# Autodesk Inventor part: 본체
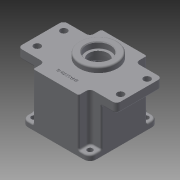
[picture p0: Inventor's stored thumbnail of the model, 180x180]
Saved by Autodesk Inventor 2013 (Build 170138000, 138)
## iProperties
Created: 2015-07
Part Number: 본체
Material: 일반
Document SubType Name: Modeling
Designer: user
Density: 1 g/cm^3
Author: user
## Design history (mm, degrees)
sketch "스케치1"
  geometry: L1 (-45, -45)-(45, -45); L2 (45, -45)-(45, 45); L3 (45, 45)-(-45, 45); L4 (-45, 45)-(-45, -45); L5 (-45, -45)-(45, 45); L6 (45, -45)-(-45, 45); 1 further point
  constraints: 12 end point, 2 midpoint, 2 parallel, 1 horizontal, 1 perpendicular
  dimensions: "d0" = 90 distance of L3.end L2.end; "d1" = 90 distance of L2.end L1.end
extrude "돌출1" new body sketch "스케치1" distance "d2" = 58; taper "d3" = 0 deg
sketch "스케치2"
  geometry: L1 (65, -45)-(-65, -45); L2 (-65, -45)-(-65, 45); L3 (-65, 45)-(65, 45); L4 (65, 45)-(65, -45); L5 (65, -45)-(-65, 45); L6 (-65, -45)-(65, 45); 1 further point
  constraints: 12 end point, 2 midpoint, 2 parallel, 1 horizontal, 1 perpendicular
  dimensions: "d4" = 130 distance of L2.end L3.end; "d5" = 90 distance of L1.end L2.end
extrude "돌출2" join sketch "스케치2" distance "d6" = 12; taper "d7" = 0 deg
sketch "스케치3"
  geometry: L1 (-65, -45)-(65, -45) reference; L2 (65, -45)-(65, 45) reference; L3 (-65, 45)-(-65, -45) reference; L4 (-30, 45)-(-30, 30); L5 (-30, 30)-(-65, 30); L6 (30, 45)-(30, 30); L7 (30, 30)-(65, 30); L8 (-65, 30)-(-65, 45); L9 (-30, 45)-(-65, 45); L10 (30, 45)-(65, 45); L11 (65, 30)-(65, 45); 2 further points
  constraints: 16 end point, 5 perpendicular, 2 collinear, 2 point on line, 1 parallel
  dimensions: "d9" = 60 distance of L4.start L6.start; "d10" = 15 distance of L4.start L4.end; "d12" = 15 distance of L6.start L6.end; "d13" = 35 distance between parallel lines of L2 L6; "d14" = 65 distance from line of point (0, 45) L2; "d15" = 90 distance from line of point (0, 45) L1
extrude "돌출3" cut sketch "스케치3" distance "d16" = 63; taper "d17" = 0 deg
sketch "스케치4"
  geometry: C1 r 40 at (0, 0); 1 further point
  constraints: 1 centre point, 1 coincident
  dimensions: "d18" = 80 diameter of C1
extrude "돌출4" cut sketch "스케치4" distance "d19" = 9; taper "d20" = 0 deg
sketch "스케치5" dims "d21" = 78
  geometry: L1 (0, 0)-(0, 35); L2 (0, 0)-(24.749, 24.749); C1 r 40 at (0, 0) reference; A1 r 4 centre (24.749, 24.749) between (21.809, 27.462) and (27.462, 21.809); A2 r 4 centre (24.749, -24.749) between (27.462, -21.809) and (21.809, -27.462); A3 r 4 centre (-24.749, -24.749) between (-21.809, -27.462) and (-27.462, -21.809); A4 r 4 centre (-24.749, 24.749) between (-27.462, 21.809) and (-21.809, 27.462); A5 r 3.5 centre (-29.836, 19.238) between (-27.412, 21.762) and (-32.777, 21.134); A6 r 3.5 centre (-19.238, 29.836) between (-21.134, 32.777) and (-21.762, 27.412); A7 r 3.5 centre (29.836, 19.238) between (32.777, 21.134) and (27.412, 21.762); A8 r 3.5 centre (19.238, -29.836) between (21.134, -32.777) and (21.762, -27.412); A9 r 3.5 centre (-19.238, -29.836) between (-21.762, -27.412) and (-21.134, -32.777); A10 r 3.5 centre (-29.836, -19.238) between (-32.777, -21.134) and (-27.412, -21.762); A11 r 3.5 centre (29.836, -19.238) between (27.412, -21.762) and (32.777, -21.134); A12 r 3.5 centre (19.238, 29.836) between (21.762, 27.412) and (21.134, 32.777); 1 further point
  constraints: 32 point on circle, 12 centre point, 8 tangent, 4 end point, 3 coincident, 1 point on line, 1 vertical, 22 other
  dimensions: "d23" = 45 deg angle of L2 L1; "d24" = 8 diameter of A1; "d25" = 8 diameter of A2; "d26" = 8 diameter of A3; "d27" = 8 diameter of A4; "d28" = 49.49747 distance of L2.end A2.centre; "d29" = 49.49747 distance of A4.centre L2.end; "d30" = 7 diameter of A5; "d31" = 7 diameter of A6; "d32" = 7 diameter of A7; "d33" = 7 diameter of A8; "d34" = 7 diameter of A9; "d35" = 7 diameter of A10; "d36" = 7 diameter of A11; "d37" = 7 diameter of A12; "d38" = 3.99472 distance from line of A7.end L2; "d39" = 34.77128 distance from line of A11.start L2; "d40" = 3.99472 distance from line of A12.start L2; "d41" = 34.77128 distance from line of A8.end L2; "d42" = 24.74874 distance from line of L1.end L2; "d43" = 34.77128 distance from line of A6.end L2; "d44" = 3.99472 distance from line of A9.start L2; "d45" = 34.77128 distance from line of A5.start L2; "d46" = 3.99472 distance from line of A10.end L2
extrude "돌출5" cut sketch "스케치5" distance "d47" = 52; taper "d48" = 0 deg
sketch "스케치6"
  geometry: L1 (30, 45)-(30, 30) reference; L2 (30, 30)-(65, 30) reference; L3 (65, 30)-(65, -30) reference; L4 (65, -30)-(30, -30) reference; L5 (30, -30)-(30, -45) reference; L6 (30, -45)-(-30, -45) reference; L7 (-30, -45)-(-30, -30) reference; L8 (-30, -30)-(-65, -30) reference; L9 (-65, -30)-(-65, 30) reference; L10 (-65, 30)-(-30, 30) reference; L11 (-30, 30)-(-30, 45) reference; L12 (-30, 45)-(30, 45) reference; L13 (-39, 0)-(39, 0); L14 (-126.492, 11)-(126.492, 11); L15 (-126.492, -20)-(126.492, -20); A1 r 4 centre (-24.749, 24.749) between (-27.462, 21.809) and (-21.809, 27.462) reference; A2 r 3.5 centre (-29.836, 19.238) between (-27.462, 21.809) and (-32.777, 21.134) reference; A3 r 39 centre (0, 0) between (-32.777, 21.134) and (-32.777, -21.134) reference; A4 r 3.5 centre (-29.836, -19.238) between (-32.777, -21.134) and (-27.462, -21.809) reference; A5 r 4 centre (-24.749, -24.749) between (-21.809, -27.462) and (-27.462, -21.809) reference; A6 r 3.5 centre (-19.238, -29.836) between (-21.809, -27.462) and (-21.134, -32.777) reference; A7 r 39 centre (0, 0) between (-21.134, -32.777) and (21.134, -32.777) reference; A8 r 3.5 centre (19.238, -29.836) between (21.134, -32.777) and (21.809, -27.462) reference; A9 r 4 centre (24.749, -24.749) between (27.462, -21.809) and (21.809, -27.462) reference; A10 r 3.5 centre (29.836, -19.238) between (27.462, -21.809) and (32.777, -21.134) reference; A11 r 39 centre (0, 0) between (32.777, -21.134) and (32.777, 21.134) reference; A12 r 3.5 centre (29.836, 19.238) between (32.777, 21.134) and (27.462, 21.809) reference; A13 r 4 centre (24.749, 24.749) between (21.809, 27.462) and (27.462, 21.809) reference; A14 r 3.5 centre (19.238, 29.836) between (21.809, 27.462) and (21.134, 32.777) reference; A15 r 39 centre (0, 0) between (21.134, 32.777) and (-21.134, 32.777) reference; A16 r 3.5 centre (-19.238, 29.836) between (-21.134, 32.777) and (-21.809, 27.462) reference; A17 r 20.5 centre (0, 11) between (7.402, -8.117) and (-7.402, -8.117); A18 r 14 centre (0, -20) between (-7.402, -8.117) and (7.402, -8.117)
  constraints: 6 end point, 6 point on circle, 2 centre point, 2 midpoint, 2 parallel
  dimensions: "d49" = 11 distance between parallel lines of L13 L14; "d51" = 20 distance between parallel lines of L15 L13; "d52" = 41 diameter of A17; "d53" = 28 diameter of A18
extrude "돌출6" join sketch "스케치6" distance "d54" = 7; taper "d55" = 0 deg
fillet "모깎기1" dims "d56" = 3
fillet "모깎기2" dims "d57" = 3
sketch "스케치7"
  geometry: C1 r 17.5 at (0, 11); A1 r 20.5 centre (0, 11) between (11.115, -6.225) and (-11.115, -6.225) reference; 1 further point
  constraints: 1 centre point, 1 coincident
  dimensions: "d58" = 35 diameter of C1
extrude "돌출7" cut sketch "스케치7" distance "d59" = 10; taper "d60" = 0 deg
sketch "스케치8"
  geometry: C1 r 17.5 at (0, 0) reference; C2 r 12.5 at (0, 0); 1 further point
  constraints: 1 centre point, 1 coincident
  dimensions: "d61" = 25 diameter of C2
extrude "돌출8" cut sketch "스케치8" distance "d62" = 5; taper "d63" = 0 deg
sketch "스케치9"
  geometry: C1 r 12.5 at (0, 0) reference; C2 r 16 at (0, 0); 1 further point
  constraints: 1 centre point, 1 coincident
  dimensions: "d64" = 32 diameter of C2
extrude "돌출9" cut sketch "스케치9" distance "d65" = 8; taper "d66" = 0 deg
sketch "스케치10"
  geometry: C1 r 16 at (0, 11) reference; C2 r 25 at (0, 11); 1 further point
  constraints: 1 centre point, 1 coincident
  dimensions: "d67" = 50 diameter of C2
extrude "돌출10" join sketch "스케치10" distance "d68" = 7; taper "d69" = 0 deg
sketch "스케치11"
  geometry: A1 r 4 centre (-24.749, 24.749) between (-27.462, 21.809) and (-21.809, 27.462) reference; A2 r 4 centre (24.749, 24.749) between (21.809, 27.462) and (27.462, 21.809) reference; A3 r 4 centre (24.749, -24.749) between (27.462, -21.809) and (21.809, -27.462) reference; A4 r 4 centre (-24.749, -24.749) between (-21.809, -27.462) and (-27.462, -21.809) reference
hole "구멍1" sketch "스케치11" at (-24.749, 24.749), (-24.749, -24.749), (24.749, -24.749), (24.749, 24.749) diameter "d70" = 3.459; stored, may be unused: countersink angle "d74" = 90 deg, drill point angle "d76" = 118 deg; dims "d71" = 12, "d72" = 4, "d73" = 2, "d75" = 15
fillet "모깎기3" dims "d77" = 8
sketch "스케치12"
  geometry: A1 r 8 centre (-37, 37) between (-37, 45) and (-45, 37) reference; A2 r 8 centre (-37, -37) between (-45, -37) and (-37, -45) reference; A3 r 8 centre (37, -37) between (37, -45) and (45, -37) reference; A4 r 8 centre (37, 37) between (45, 37) and (37, 45) reference
hole "구멍2" sketch "스케치12" at (-37, 37), (37, 37), (37, -37), (-37, -37) diameter "d78" = 7; stored, may be unused: countersink angle "d82" = 90 deg, drill point angle "d84" = 118 deg; dims "d79" = 12, "d80" = 4, "d81" = 2, "d83" = 15
fillet "모깎기4" dims "d85" = 5
sketch "스케치13"
  geometry: L1 (60, 30)-(30, 30) reference; L2 (65, -25)-(65, 25) reference; L3 (-53.488, -16.104)-(56.512, -16.104); L4 (56.512, -16.104)-(56.512, 18.896); L5 (56.512, 18.896)-(-53.488, 18.896); L6 (-53.488, 18.896)-(-53.488, -16.104); L7 (-53.488, -16.104)-(56.512, 18.896); L8 (56.512, -16.104)-(-53.488, 18.896); 6 further points
  constraints: 12 end point, 4 coincident, 2 midpoint, 2 parallel, 1 horizontal, 1 perpendicular
  dimensions: "d86" = 110 distance of L5.end L4.end; "d87" = 35 distance of L4.end L3.end; "d88" = 118.48778 distance between parallel lines of L2 L6; "d89" = 11.1041 distance between parallel lines of L1 L5
hole "구멍3" sketch "스케치13" at (-53.488, 18.896), (-53.488, -16.104), (56.512, -16.104), (56.512, 18.896) diameter "d90" = 9; stored, may be unused: countersink angle "d94" = 90 deg, drill point angle "d96" = 118 deg; dims "d91" = 12, "d92" = 4, "d93" = 2, "d95" = 15
sketch "스케치14"
  geometry: C1 r 11 at (0, -20); A1 r 14 centre (0, -20) between (-10.493, -10.732) and (10.493, -10.732) reference; 1 further point
  constraints: 1 centre point, 1 coincident
  dimensions: "d97" = 22 diameter of C1
extrude "돌출11" cut sketch "스케치14" distance "d98" = 7; taper "d99" = 0 deg
sketch "스케치15"
  geometry: C1 r 11 at (0, 0) reference; C2 r 9.5 at (0, 0); 1 further point
  constraints: 1 centre point, 1 coincident
  dimensions: "d100" = 19 diameter of C2
extrude "돌출12" cut sketch "스케치15" distance "d101" = 1; taper "d102" = 0 deg
fillet "모깎기6" dims "d104" = 2
chamfer "모따기1" distance "d105" = 1; stored, may be unused: second distance "d106" = 2, angle "d107" = 45 deg
chamfer "모따기2" distance "d108" = 1; stored, may be unused: second distance "d109" = 2, angle "d110" = 45 deg
fillet "모깎기8" dims "d112" = 2
fillet "모깎기9" dims "d113" = 2
sketch "스케치16"
  geometry: L1 (-30, -45)-(30, -45) reference; L2 (0, 11)-(0, -45); C1 r 25 at (0, 11) reference; 4 further points
  constraints: 2 end point, 1 midpoint, 1 point on line, 1 other
  dimensions: "d117" = 15 distance from line of L1 point (0, -30)
feature "엠보싱1" sketch "스케치16" dims "d118" = 0.5, "d119" = 0
fillet "모깎기13" dims "d120" = 2
fillet "모깎기14" dims "d121" = 5
fillet "모깎기15" dims "d122" = 5
fillet "모깎기16" dims "d123" = 2
fillet "모깎기17" dims "d124" = 2
fillet "모깎기19" dims "d126" = 0.3
fillet "모깎기20" dims "d127" = 0.3
fillet "모깎기21" dims "d128" = 2
fillet "모깎기22" dims "d129" = 2
node "솔리드1"
mirror "대칭1"
node "절단 모서리 투영1"
